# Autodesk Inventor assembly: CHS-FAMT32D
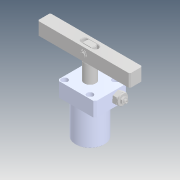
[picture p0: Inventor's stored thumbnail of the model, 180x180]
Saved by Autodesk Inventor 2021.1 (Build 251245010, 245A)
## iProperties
Created: 2020-02
Part Number: CHS-FAMT32D
Description: STEP AP214
Document SubType Name: Assembly
Designer: user
Title: chs-famt32d_asm.STEP
Revision Number: ÈÎºÎ
Sending System: SolidWorks 2016
Preprocessor: SwSTEP 2.0
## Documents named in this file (9)
- D:\Vault_2016\Projekty\Clamptek\Hydraulic\CHS\CHS-32\Inventor\CHS-FAMT32D\CHS-FAMT32D.iam
- D:\Vault_2016\Projekty\Clamptek\Hydraulic\CHS\CHS-32\Inventor\CHS-FAMT32D\CHS-32D-02_3_1.ipt
- D:\Vault_2016\Projekty\Clamptek\Hydraulic\CHS\CHS-32\Inventor\CHS-FAMT32D\CHS-32D-01_4.ipt
- D:\Vault_2016\Projekty\Clamptek\Hydraulic\CHS\CHS-32\Inventor\CHS-FAMT32D\CHS-FAMT32BT.ipt
- D:\Vault_2016\Projekty\Clamptek\Hydraulic\CHS\CHS-32\Inventor\CHS-FAMT32D\Öá8µ²È¦_1.ipt
- D:\Vault_2016\Projekty\Clamptek\Hydraulic\CHS\CHS-32\Inventor\CHS-FAMT32D\Xiaozhou_1.ipt
- D:\Vault_2016\Projekty\Clamptek\Hydraulic\CHS\CHS-32\Inventor\CHS-FAMT32D\20·§Ìå.ipt
- D:\Vault_2016\Projekty\Clamptek\Hydraulic\CHS\CHS-32\Inventor\CHS-FAMT32D\20µ÷ËÙ¸Ë.ipt
- D:\Vault_2016\Projekty\Clamptek\Hydraulic\CHS\CHS-32\Inventor\CHS-FAMT32D\hex thin nuts-grades ab-chamfered gb(GB_FASTENER_NUT_STNAB M6-S).ipt
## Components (9 placed, 9 different names)
1. CHS-32D-02_3_1_1
2. CHS-32D-01_4_2
3. CHS-FAMT32BT_3
4. Öá8µ²È¦_1_4
5. Xiaozhou_1_5
6. 20·§Ìå_6
7. 20µ÷ËÙ¸Ë_7
8. hex thin nuts-grades ab-chamfered gb(GB_FASTENER_NUT_STNAB M6-S)_8
9. Öá8µ²È¦_1_9
